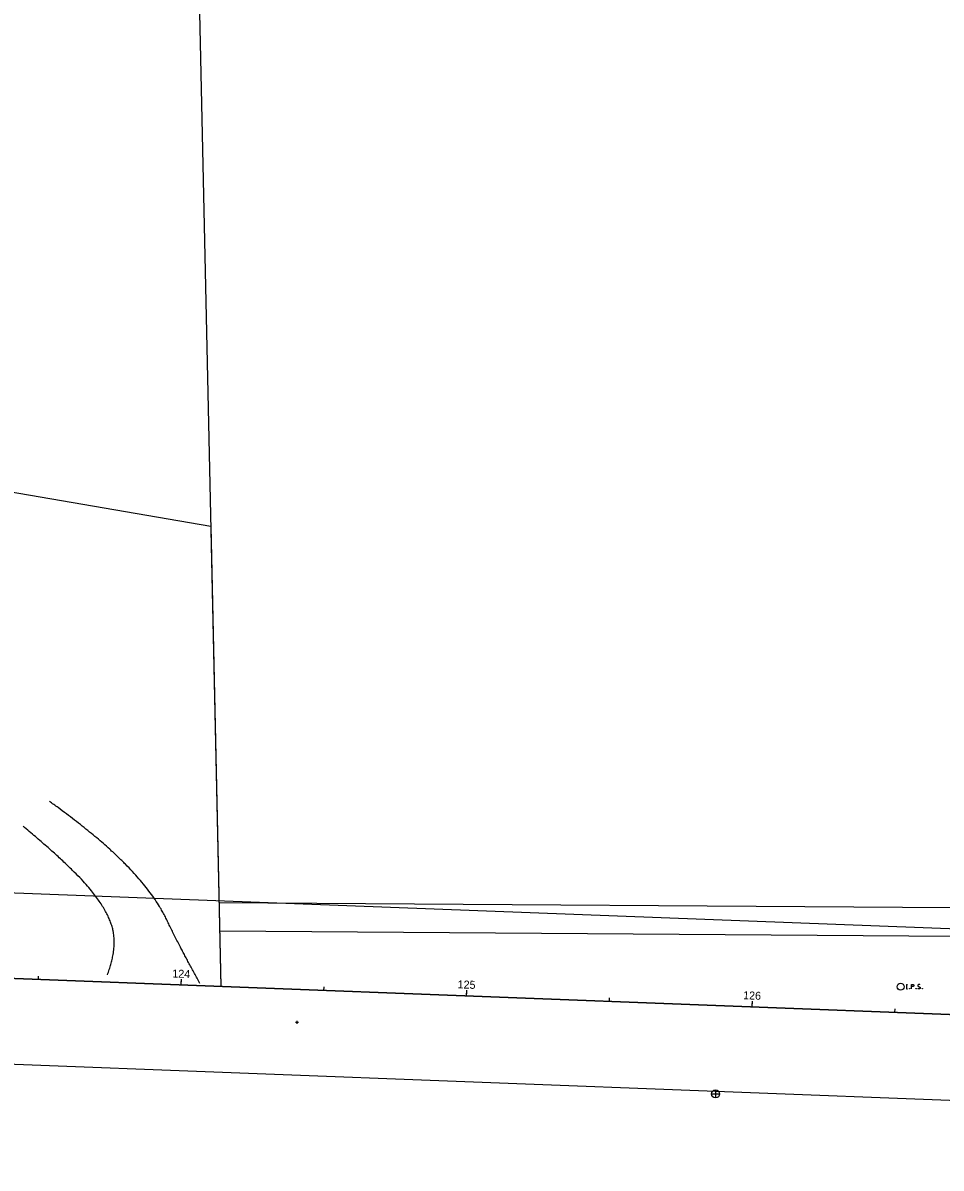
# Model space of a CAD drawing. Extents: x 2003596 to 2006933, y 570827 to 573780.
# Drawn here: x 2005079.1 to 2005400.5, y 572567.3 to 572968 of the extents above; entities that cross this region are included whole.
import ezdxf

# ---------------------------------------------------------------- set-up
doc = ezdxf.new("R2010")
doc.units = 0
for name, color, linetype in [('DT_X_Void', 7, 'Continuous'), ('DV_X_Property_Line', 7, 'Continuous'), ('GE_X_Alignment', 7, 'Continuous'), ('GE_X_Alignment_1000_Stations', 7, 'Continuous'), ('GE_X_Alignment_100_Stations', 7, 'Continuous'), ('GE_X_Alignment_500_Stations', 7, 'Continuous'), ('RW_X_CL', 7, 'Continuous'), ('RW_X_Esmt_SH', 7, 'Continuous'), ('SV_P_Mon_Cells_Set', 7, 'Continuous'), ('SV_X_Control_Cells_Found', 7, 'Continuous'), ('SV_X_Shot_Marker', 7, 'Continuous'), ('UT_X_Telecom', 7, 'Continuous')]:
    doc.layers.add(name, color=color, linetype=linetype)

msp = doc.modelspace()

# ---------------------------------------------------------------- linework, layer by layer
at = {"layer": 'DT_X_Void'}
for points in [[(2005141.06, 572631.9), (2005133.69, 572645.19), (2005125.13, 572663.26), (2005105.22, 572683.53), (2005088.35, 572695.61)], [(2005108.67, 572634.92), (2005111.96, 572643.66), (2005109.5, 572656.37), (2005096.52, 572672.43), (2005079.15, 572686.9)]]:
    msp.add_open_spline(points, degree=2, dxfattribs=at)
at = {"layer": 'DV_X_Property_Line'}
for p, q in [((2005130.17, 573462.44), (2005148.41, 572630.83)), ((2004942.56, 572826.68), (2005144.88, 572791.94)), ((2005144.88, 572791.94), (2005148.41, 572630.83))]:
    msp.add_line(p, q, dxfattribs=at)
at = {"layer": 'GE_X_Alignment'}
msp.add_line((2005031.48, 572635.32), (2006023.62, 572597.25), dxfattribs=at)
at = {"layer": 'GE_X_Alignment_1000_Stations'}
msp.add_line((2005234.4, 572627.53), (2005234.45, 572628.73), dxfattribs=at)
at = {"layer": 'GE_X_Alignment_100_Stations'}
for p, q in [((2005084.51, 572633.28), (2005084.56, 572634.48)), ((2005134.47, 572631.37), (2005134.55, 572633.37)), ((2005184.44, 572629.45), (2005184.48, 572630.65)), ((2005234.4, 572627.53), (2005234.48, 572629.53)), ((2005284.36, 572625.62), (2005284.41, 572626.82)), ((2005334.33, 572623.7), (2005334.4, 572625.7)), ((2005384.29, 572621.78), (2005384.34, 572622.98))]:
    msp.add_line(p, q, dxfattribs=at)
at = {"layer": 'GE_X_Alignment_500_Stations'}
for p, q in [((2005134.47, 572631.37), (2005134.52, 572632.57)), ((2005234.4, 572627.53), (2005234.48, 572629.53)), ((2005334.33, 572623.7), (2005334.37, 572624.9))]:
    msp.add_line(p, q, dxfattribs=at)
at = {"layer": 'RW_X_CL'}
msp.add_line((2006023.62, 572597.25), (2005031.48, 572635.32), dxfattribs=at)
at = {"layer": 'RW_X_Esmt_SH'}
for p, q in [((2005034.78, 572665.22), (2006024.45, 572627.24)), ((2005028.18, 572605.42), (2006022.8, 572567.26))]:
    msp.add_line(p, q, dxfattribs=at)
at = {"layer": 'SV_P_Mon_Cells_Set'}
for points in [[(2005388.32, 572631.54), (2005388.67, 572631.54)], [(2005388.49, 572629.94), (2005388.49, 572631.54)], [(2005389.45, 572630.15), (2005389.51, 572630.15), (2005389.54, 572630.13), (2005389.57, 572630.08), (2005389.57, 572630.02), (2005389.54, 572629.97), (2005389.51, 572629.94), (2005389.45, 572629.94), (2005389.42, 572629.97), (2005389.39, 572630.02), (2005389.39, 572630.08), (2005389.42, 572630.13), (2005389.45, 572630.15)], [(2005390.06, 572629.94), (2005390.06, 572631.54), (2005390.59, 572631.54), (2005390.64, 572631.53), (2005390.72, 572631.5), (2005390.75, 572631.48), (2005390.79, 572631.45), (2005390.83, 572631.39), (2005390.86, 572631.33), (2005390.88, 572631.23), (2005390.88, 572631.07), (2005390.87, 572631.02), (2005390.85, 572630.95), (2005390.81, 572630.86), (2005390.76, 572630.82), (2005390.73, 572630.8), (2005390.67, 572630.77), (2005390.59, 572630.76), (2005390.06, 572630.76)], [(2005391.7, 572630.15), (2005391.76, 572630.15), (2005391.79, 572630.13), (2005391.82, 572630.08), (2005391.82, 572630.02), (2005391.79, 572629.97), (2005391.76, 572629.94), (2005391.7, 572629.94), (2005391.67, 572629.97), (2005391.63, 572630.02), (2005391.63, 572630.08), (2005391.67, 572630.13), (2005391.7, 572630.15)], [(2005393.07, 572631.43), (2005393.05, 572631.45), (2005393.01, 572631.48), (2005392.91, 572631.52), (2005392.79, 572631.54), (2005392.7, 572631.54), (2005392.67, 572631.54), (2005392.53, 572631.5), (2005392.41, 572631.43), (2005392.33, 572631.33), (2005392.31, 572631.23), (2005392.31, 572631.15), (2005392.33, 572631.05), (2005392.42, 572630.96), (2005393.02, 572630.58), (2005393.08, 572630.53), (2005393.1, 572630.48), (2005393.12, 572630.41), (2005393.12, 572630.33), (2005393.11, 572630.26), (2005393.1, 572630.21), (2005393.08, 572630.14), (2005393.06, 572630.09), (2005393.03, 572630.05), (2005393, 572630.02), (2005392.97, 572629.99), (2005392.92, 572629.97), (2005392.89, 572629.95), (2005392.79, 572629.94), (2005392.64, 572629.94), (2005392.54, 572629.97), (2005392.39, 572630.05), (2005392.31, 572630.13)], [(2005393.88, 572630.15), (2005393.94, 572630.15), (2005393.97, 572630.13), (2005394, 572630.08), (2005394, 572630.02), (2005393.97, 572629.97), (2005393.94, 572629.94), (2005393.88, 572629.94), (2005393.85, 572629.97), (2005393.82, 572630.02), (2005393.82, 572630.08), (2005393.85, 572630.13), (2005393.88, 572630.15)], [(2005388.32, 572629.94), (2005388.67, 572629.94)]]:
    msp.add_lwpolyline(points, dxfattribs=at)
msp.add_circle((2005386.3, 572630.74), 1.2, dxfattribs=at)
at = {"layer": 'SV_X_Control_Cells_Found'}
for p, q in [((2005321.51, 572594.62), (2005321.51, 572591.8)), ((2005320.1, 572593.21), (2005322.92, 572593.21))]:
    msp.add_line(p, q, dxfattribs=at)
msp.add_circle((2005321.51, 572593.21), 1.41, dxfattribs=at)
at = {"layer": 'SV_X_Shot_Marker'}
for p, q in [((2005174.5, 572618.29), (2005175.5, 572618.29)), ((2005175, 572618.79), (2005175, 572617.79)), ((2005175, 572618.29), (2005175, 572618.29))]:
    msp.add_line(p, q, dxfattribs=at)
at = {"layer": 'UT_X_Telecom'}
for points in [[(2005147.76, 572660.26), (2005421.1, 572658.32), (2005446.17, 572659.8), (2005471.38, 572659.28), (2005497.09, 572658.54), (2005522.25, 572656.73), (2005547.24, 572652.92), (2005571.87, 572650.16), (2005596.85, 572649.37), (2005621.79, 572646.67), (2006021.03, 572631.61)], [(2005147.98, 572650.26), (2005421.36, 572648.31), (2005446.36, 572649.8), (2005471.14, 572649.29), (2005496.59, 572648.55), (2005521.14, 572646.78), (2005545.93, 572643), (2005571.15, 572640.18), (2005596.15, 572639.39), (2005621.06, 572636.69), (2006021.19, 572621.6)]]:
    msp.add_lwpolyline(points, dxfattribs=at)

# ---------------------------------------------------------------- texts
at = {"layer": 'GE_X_Alignment_100_Stations'}
for s, p in [('124', (2005131.33, 572633.99)), ('125', (2005231.21, 572630.2)), ('126', (2005331.14, 572626.37))]:
    msp.add_text(s, height=2.8, rotation=357.8026, dxfattribs=at).set_placement(p)
at = {"layer": 'GE_X_Alignment_500_Stations'}
msp.add_text('125', height=2.8, rotation=357.8026, dxfattribs=at).set_placement((2005231.21, 572630.2))

doc.saveas('drawing.dxf')
